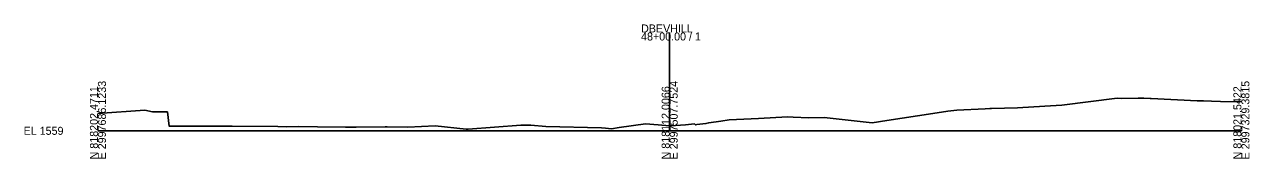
# Model space of a CAD drawing. Extents: x -26 to 2003, y -10 to 2160.
# Drawn here: x -25.7 to 402.8, y -9.7 to 37.2 of the extents above; entities that cross this region are included whole.
import ezdxf

# ---------------------------------------------------------------- set-up
doc = ezdxf.new("R2010")
doc.units = 0
doc.layers.add('DESIGN - SHEET - Light Grid', color=7, linetype='Continuous')
doc.layers.add('SURVEY - GROUND - Top of Ground', color=7, linetype='Continuous')

msp = doc.modelspace()

# ---------------------------------------------------------------- linework, layer by layer
at = {"layer": 'DESIGN - SHEET - Light Grid'}
for p, q in [((200, 0), (200, 34.42)), ((0, 0), (200, 0)), ((200, 0), (400, 0))]:
    msp.add_line(p, q, dxfattribs=at)
at = {"layer": 'SURVEY - GROUND - Top of Ground'}
msp.add_lwpolyline([(0, 6.02), (16.35, 7.22), (19.04, 6.65), (24.29, 6.63), (24.88, 1.64), (39.16, 1.63), (42.56, 1.59), (44.63, 1.64), (46.94, 1.68), (62.97, 1.46), (65.99, 1.42), (70.17, 1.46), (76.77, 1.34), (86.61, 1.31), (90.36, 1.31), (100.44, 1.44), (101.16, 1.43), (108.38, 1.31), (117.93, 1.77), (128.87, 0.59), (129.46, 0.6), (147.96, 1.96), (151.44, 2.01), (156.66, 1.46), (176.1, 1.05), (177.56, 0.96), (179.64, 0.74), (182.29, 1.12), (191.52, 2.47), (195.95, 2.07), (200, 1.73), (200.33, 1.71), (205.56, 2.13), (208.69, 2.42), (209.02, 2.08), (209.48, 2.21), (212.67, 2.54), (213.67, 2.81), (217.89, 3.35), (220.78, 3.81), (231.1, 4.34), (241.23, 4.89), (243.26, 4.76), (248.72, 4.49), (254, 4.66), (270.81, 2.85), (275.99, 3.6), (292.01, 6.01), (297.36, 6.85), (300.42, 7.27), (310.39, 7.71), (312.06, 7.81), (312.64, 7.82), (321.68, 8.05), (331.25, 8.59), (337.21, 8.97), (356.51, 11.47), (358.22, 11.35), (363.85, 11.47), (365.83, 11.39), (368.1, 11.28), (368.42, 11.27), (384.56, 10.52), (386.78, 10.45), (389.59, 10.36), (392.71, 10.24), (400, 10.14)], dxfattribs=at)

# ---------------------------------------------------------------- texts
at = {"layer": 'DESIGN - SHEET - Light Grid'}
for s, p in [('48+00.00 / 1', (190, 31.62)), ('DBEVHILL', (190, 34.42)), ('EL 1559', (-26, -1.4))]:
    msp.add_text(s, height=2.8, dxfattribs=at).set_placement(p)
for s, p in [('E 2997686.1233', (2.8, -10)), ('E 2997507.7524', (202.8, -10)), ('E 2997329.3815', (402.8, -10)), ('N 818202.4711', (0, -10)), ('N 818112.0066', (200, -10)), ('N 818021.5422', (400, -10))]:
    msp.add_text(s, height=2.8, rotation=90, dxfattribs=at).set_placement(p)

doc.saveas('drawing.dxf')
